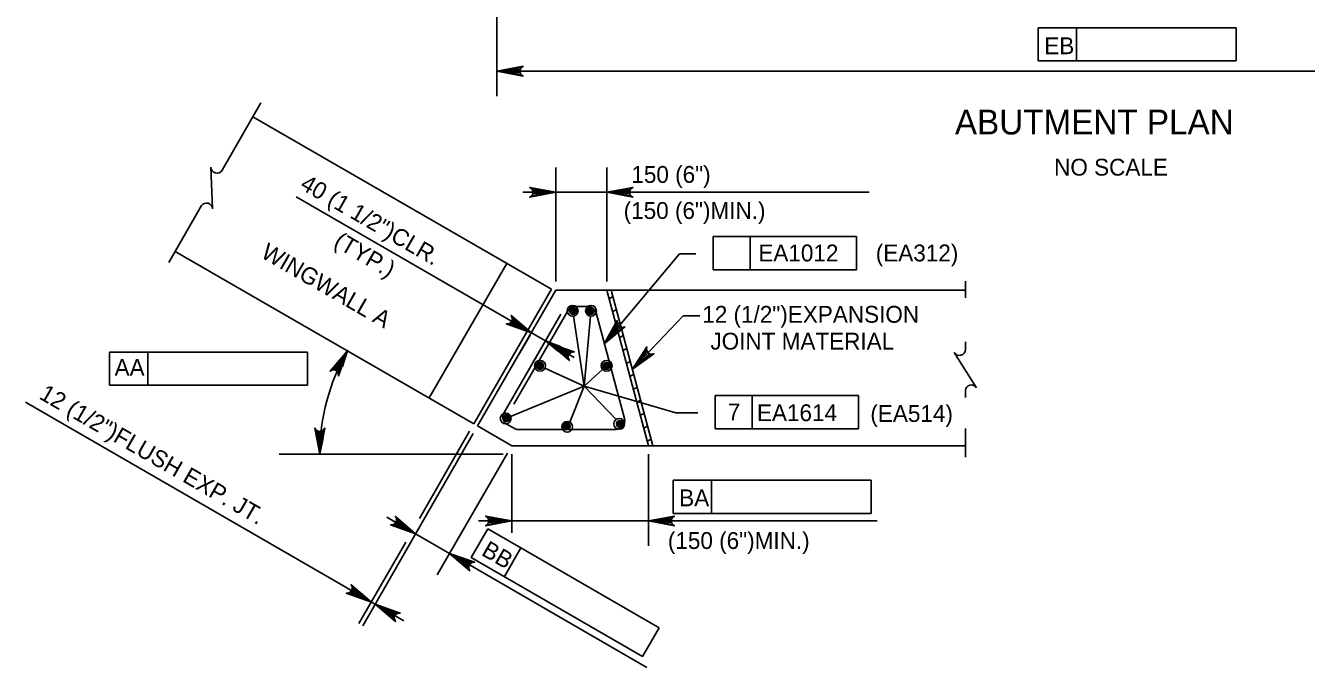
# Model space of a CAD drawing. Extents: x 634540 to 640306, y 296059 to 300275.
# Drawn here: x 638529.9 to 638758.2, y 298120 to 298234.3 of the extents above; entities that cross this region are included whole.
import ezdxf

# ---------------------------------------------------------------- set-up
doc = ezdxf.new("R2010")
doc.units = 0
for name, color, linetype in [('10', 7, 'Continuous'), ('3', 7, 'Continuous'), ('4', 7, 'Continuous'), ('5', 7, 'Continuous')]:
    doc.layers.add(name, color=color, linetype=linetype)

msp = doc.modelspace()

# ---------------------------------------------------------------- linework, layer by layer
at = {"layer": '10'}
for p, q in [((638623.63, 298187.38), (638570.4, 298218.11)), ((638609.79, 298163.4), (638556.56, 298194.13)), ((638615.64, 298191.99), (638601.8, 298168.01)), ((638623.63, 298187.38), (638609.79, 298163.4)), ((638624.41, 298187.19), (638610.45, 298163.02)), ((638697.41, 298187.19), (638624.41, 298187.19)), ((638633.47, 298187.19), (638640.89, 298159.51)), ((638634.27, 298187.19), (638641.69, 298159.51)), ((638634.57, 298186.06), (638633.88, 298185.67)), ((638635.19, 298183.76), (638634.5, 298183.36)), ((638635.81, 298181.45), (638635.12, 298181.05)), ((638636.42, 298179.14), (638635.73, 298178.74)), ((638637.04, 298176.84), (638636.35, 298176.44)), ((638637.66, 298174.53), (638636.97, 298174.13)), ((638638.28, 298172.22), (638637.59, 298171.82)), ((638638.9, 298169.91), (638638.21, 298169.52)), ((638639.51, 298167.61), (638638.82, 298167.21)), ((638640.13, 298165.3), (638639.44, 298164.9)), ((638616.53, 298159.51), (638610.45, 298163.02)), ((638640.75, 298162.99), (638640.06, 298162.6)), ((638697.41, 298159.51), (638616.53, 298159.51)), ((638641.37, 298160.69), (638640.68, 298160.29))]:
    msp.add_line(p, q, dxfattribs=at)
at = {"layer": '3'}
for p, q in [((638613.9, 298270.52), (638613.9, 298221.78)), ((638710.38, 298233.94), (638717.22, 298233.94)), ((638710.38, 298228.04), (638710.38, 298233.94)), ((638717.22, 298228.04), (638717.22, 298233.94)), ((638717.22, 298233.94), (638745.68, 298233.94)), ((638745.68, 298233.94), (638745.68, 298228.04)), ((638745.68, 298228.04), (638710.38, 298228.04)), ((638613.9, 298226.21), (638842.16, 298226.21)), ((638624.41, 298188.73), (638624.41, 298209.09)), ((638633.47, 298188.73), (638633.47, 298209.09)), ((638624.41, 298204.66), (638618.51, 298204.66)), ((638633.47, 298204.66), (638624.41, 298204.66)), ((638633.47, 298204.66), (638680.27, 298204.66)), ((638614.93, 298182.57), (638578.12, 298203.82)), ((638652.45, 298196.76), (638677.99, 298196.76)), ((638652.45, 298190.86), (638652.45, 298196.76)), ((638659.04, 298190.86), (638659.04, 298196.76)), ((638677.99, 298196.76), (638677.99, 298190.86)), ((638633.04, 298177.65), (638646.42, 298193.7)), ((638646.42, 298193.7), (638649.37, 298193.7)), ((638677.99, 298190.86), (638652.45, 298190.86)), ((638620.04, 298179.62), (638614.93, 298182.57)), ((638629.44, 298170.14), (638627.53, 298182.58)), ((638630.58, 298182.58), (638629.44, 298170.14)), ((638638.04, 298173.12), (638647.08, 298182.63)), ((638647.08, 298182.63), (638650.04, 298182.63)), ((638622.54, 298178.18), (638620.04, 298179.62)), ((638619.8, 298179.2), (638617.83, 298175.78)), ((638622.3, 298177.76), (638620.32, 298174.34)), ((638623.21, 298177.79), (638627.65, 298175.23)), ((638544.82, 298176.19), (638551.67, 298176.19)), ((638544.82, 298170.28), (638544.82, 298176.19)), ((638551.67, 298170.28), (638551.67, 298176.19)), ((638551.67, 298176.19), (638580.13, 298176.19)), ((638580.13, 298170.28), (638580.13, 298176.19)), ((638629.44, 298170.14), (638622.46, 298173.34)), ((638632.74, 298173.1), (638629.44, 298170.14)), ((638580.13, 298170.28), (638544.82, 298170.28)), ((638629.44, 298170.14), (638616.34, 298164.72)), ((638626.89, 298163.71), (638629.44, 298170.14)), ((638629.44, 298170.14), (638645.77, 298165.38)), ((638635.15, 298164.18), (638629.44, 298170.14)), ((638652.79, 298168.44), (638678.33, 298168.44)), ((638652.79, 298162.54), (638652.79, 298168.44)), ((638659.39, 298162.54), (638659.39, 298168.44)), ((638678.33, 298168.44), (638678.33, 298162.54)), ((638586.4, 298134.61), (638529.88, 298167.24)), ((638645.77, 298165.38), (638649.72, 298165.38)), ((638609.69, 298161.69), (638589.97, 298127.44)), ((638609.02, 298162.07), (638600.09, 298146.55)), ((638678.33, 298162.54), (638652.79, 298162.54)), ((638615, 298157.97), (638575.09, 298157.97)), ((638615.77, 298158.17), (638603.24, 298136.49)), ((638616.53, 298157.97), (638616.53, 298143.98)), ((638640.89, 298157.97), (638640.89, 298141.68)), ((638645.3, 298147.44), (638645.3, 298153.35)), ((638645.3, 298153.35), (638652.14, 298153.35)), ((638652.14, 298147.44), (638652.14, 298153.35)), ((638652.14, 298153.35), (638680.6, 298153.35)), ((638680.6, 298153.35), (638680.6, 298147.44)), ((638680.6, 298147.44), (638645.3, 298147.44)), ((638596.82, 298145.31), (638594.27, 298146.79)), ((638613.58, 298146.11), (638610.63, 298146.11)), ((638616.53, 298146.11), (638640.89, 298146.11)), ((638643.84, 298146.11), (638646.79, 298146.11)), ((638646.79, 298146.11), (638681.66, 298146.11)), ((638599.38, 298143.83), (638605.46, 298140.32)), ((638609.3, 298139.6), (638612.25, 298144.72)), ((638612.25, 298144.72), (638618.18, 298141.3)), ((638597.66, 298142.34), (638589.3, 298127.82)), ((638615.23, 298136.18), (638618.18, 298141.3)), ((638618.18, 298141.3), (638642.83, 298127.07)), ((638608.01, 298138.85), (638610.57, 298137.37)), ((638639.87, 298121.95), (638609.3, 298139.6)), ((638610.57, 298137.37), (638640.63, 298120.02)), ((638588.96, 298133.13), (638586.4, 298134.61)), ((638592.18, 298131.27), (638591.52, 298131.65)), ((638594.74, 298129.79), (638597.3, 298128.32)), ((638642.83, 298127.07), (638639.87, 298121.95))]:
    msp.add_line(p, q, dxfattribs=at)
for points in [[(638613.9, 298226.21), (638618.56, 298227.09), (638618.2, 298226.84), (638618.01, 298226.53), (638617.96, 298226.21), (638618.01, 298225.9), (638618.2, 298225.59), (638618.56, 298225.34), (638613.9, 298226.21), (638618.2, 298225.59), (638618.01, 298225.9), (638613.9, 298226.21), (638617.96, 298226.21), (638618.01, 298226.53), (638613.9, 298226.21), (638618.2, 298226.84)], [(638624.41, 298204.66), (638619.75, 298203.79), (638620.11, 298204.04), (638620.29, 298204.35), (638620.35, 298204.66), (638620.29, 298204.97), (638620.11, 298205.29), (638619.75, 298205.53), (638624.41, 298204.66), (638620.11, 298205.29), (638620.29, 298204.97), (638624.41, 298204.66), (638620.35, 298204.66), (638620.29, 298204.35), (638624.41, 298204.66), (638620.11, 298204.04)], [(638633.47, 298204.66), (638638.13, 298205.53), (638637.77, 298205.29), (638637.59, 298204.97), (638637.53, 298204.66), (638637.59, 298204.35), (638637.77, 298204.04), (638638.13, 298203.79), (638633.47, 298204.66), (638637.77, 298204.04), (638637.59, 298204.35), (638633.47, 298204.66), (638637.53, 298204.66), (638637.59, 298204.97), (638633.47, 298204.66), (638637.77, 298205.29)], [(638620.04, 298179.62), (638615.57, 298181.19), (638616, 298181.23), (638616.32, 298181.41), (638616.52, 298181.65), (638616.63, 298181.95), (638616.63, 298182.31), (638616.44, 298182.71), (638620.04, 298179.62), (638616.63, 298182.31), (638616.63, 298181.95), (638620.04, 298179.62), (638616.52, 298181.65), (638616.32, 298181.41), (638620.04, 298179.62), (638616, 298181.23)], [(638633.04, 298177.65), (638635.35, 298181.79), (638635.31, 298181.36), (638635.43, 298181.01), (638635.64, 298180.77), (638635.91, 298180.61), (638636.27, 298180.56), (638636.7, 298180.67), (638633.04, 298177.65), (638636.27, 298180.56), (638635.91, 298180.61), (638633.04, 298177.65), (638635.64, 298180.77), (638635.43, 298181.01), (638633.04, 298177.65), (638635.31, 298181.36)], [(638623.21, 298177.79), (638627.68, 298176.22), (638627.24, 298176.18), (638626.93, 298176), (638626.72, 298175.76), (638626.61, 298175.46), (638626.62, 298175.1), (638626.81, 298174.7), (638623.21, 298177.79), (638626.62, 298175.1), (638626.61, 298175.46), (638623.21, 298177.79), (638626.72, 298175.76), (638626.93, 298176), (638623.21, 298177.79), (638627.24, 298176.18)], [(638587.25, 298176.41), (638585.68, 298171.94), (638585.64, 298172.38), (638585.46, 298172.69), (638585.22, 298172.89), (638584.92, 298173), (638584.56, 298173), (638584.16, 298172.81), (638587.25, 298176.41), (638584.56, 298173), (638584.92, 298173), (638587.25, 298176.41), (638585.22, 298172.89), (638585.46, 298172.69), (638587.25, 298176.41), (638585.64, 298172.38)], [(638638.04, 298173.12), (638640.62, 298177.1), (638640.55, 298176.67), (638640.65, 298176.32), (638640.84, 298176.06), (638641.1, 298175.89), (638641.45, 298175.8), (638641.88, 298175.89), (638638.04, 298173.12), (638641.45, 298175.8), (638641.1, 298175.89), (638638.04, 298173.12), (638640.84, 298176.06), (638640.65, 298176.32), (638638.04, 298173.12), (638640.55, 298176.67)], [(638582.32, 298157.97), (638581.44, 298162.63), (638581.69, 298162.27), (638582.01, 298162.09), (638582.32, 298162.03), (638582.63, 298162.09), (638582.94, 298162.27), (638583.19, 298162.63), (638582.32, 298157.97), (638582.94, 298162.27), (638582.63, 298162.09), (638582.32, 298157.97), (638582.32, 298162.03), (638582.01, 298162.09), (638582.32, 298157.97), (638581.69, 298162.27)], [(638599.4, 298143.82), (638594.93, 298145.4), (638595.36, 298145.43), (638595.68, 298145.61), (638595.88, 298145.86), (638595.99, 298146.15), (638595.99, 298146.52), (638595.8, 298146.91), (638599.4, 298143.82), (638595.99, 298146.52), (638595.99, 298146.15), (638599.4, 298143.82), (638595.88, 298145.86), (638595.68, 298145.61), (638599.4, 298143.82), (638595.36, 298145.43)], [(638616.53, 298146.11), (638611.87, 298145.24), (638612.23, 298145.48), (638612.42, 298145.8), (638612.47, 298146.11), (638612.42, 298146.42), (638612.23, 298146.73), (638611.87, 298146.98), (638616.53, 298146.11), (638612.23, 298146.73), (638612.42, 298146.42), (638616.53, 298146.11), (638612.47, 298146.11), (638612.42, 298145.8), (638616.53, 298146.11), (638612.23, 298145.48)], [(638640.89, 298146.11), (638645.55, 298146.98), (638645.19, 298146.73), (638645.01, 298146.42), (638644.95, 298146.11), (638645.01, 298145.8), (638645.19, 298145.48), (638645.55, 298145.24), (638640.89, 298146.11), (638645.19, 298145.48), (638645.01, 298145.8), (638640.89, 298146.11), (638644.95, 298146.11), (638645.01, 298146.42), (638640.89, 298146.11), (638645.19, 298146.73)], [(638605.46, 298140.32), (638609.93, 298138.75), (638609.5, 298138.72), (638609.18, 298138.54), (638608.98, 298138.29), (638608.87, 298138), (638608.87, 298137.63), (638609.06, 298137.24), (638605.46, 298140.32), (638608.87, 298137.63), (638608.87, 298138), (638605.46, 298140.32), (638608.98, 298138.29), (638609.18, 298138.54), (638605.46, 298140.32), (638609.5, 298138.72)], [(638591.51, 298131.66), (638587.04, 298133.23), (638587.47, 298133.27), (638587.79, 298133.45), (638587.99, 298133.69), (638588.1, 298133.99), (638588.1, 298134.35), (638587.91, 298134.75), (638591.51, 298131.66), (638588.1, 298134.35), (638588.1, 298133.99), (638591.51, 298131.66), (638587.99, 298133.69), (638587.79, 298133.45), (638591.51, 298131.66), (638587.47, 298133.27)], [(638592.19, 298131.26), (638596.67, 298129.69), (638596.23, 298129.66), (638595.91, 298129.48), (638595.71, 298129.24), (638595.6, 298128.94), (638595.61, 298128.58), (638595.79, 298128.18), (638592.19, 298131.26), (638595.61, 298128.58), (638595.6, 298128.94), (638592.19, 298131.26), (638595.71, 298129.24), (638595.91, 298129.48), (638592.19, 298131.26), (638596.23, 298129.66)]]:
    msp.add_lwpolyline(points, dxfattribs=at)
for points in [[(638616.85, 298226.7), (638616.85, 298225.72), (638613.9, 298226.21)], [(638621.46, 298205.15), (638621.46, 298204.17), (638624.41, 298204.66)], [(638636.42, 298205.15), (638636.42, 298204.17), (638633.47, 298204.66)], [(638617.73, 298181.52), (638617.24, 298180.67), (638620.04, 298179.62)], [(638634.55, 298180.24), (638635.31, 298179.61), (638633.04, 298177.65)], [(638625.34, 298177.13), (638624.85, 298176.28), (638622.54, 298178.18)], [(638586.34, 298173.63), (638585.47, 298174.09), (638587.28, 298176.47)], [(638639.71, 298175.6), (638640.43, 298174.92), (638638.04, 298173.12)], [(638581.94, 298160.94), (638582.93, 298160.9), (638582.32, 298157.97)], [(638597.07, 298145.74), (638596.58, 298144.88), (638599.38, 298143.83)], [(638613.58, 298146.6), (638613.58, 298145.62), (638616.53, 298146.11)], [(638643.84, 298146.6), (638643.84, 298145.62), (638640.89, 298146.11)], [(638608.26, 298139.27), (638607.77, 298138.42), (638605.46, 298140.32)], [(638589.21, 298133.56), (638588.71, 298132.7), (638591.52, 298131.65)], [(638594.98, 298130.22), (638594.49, 298129.37), (638592.18, 298131.27)]]:
    msp.add_lwpolyline(points, close=True, dxfattribs=at)
for centre in [(638627.39, 298183.54), (638630.67, 298183.54), (638621.58, 298173.75), (638633.45, 298173.75), (638615.45, 298164.35), (638626.42, 298162.87), (638635.7, 298163.39)]:
    msp.add_circle(centre, 0.962, dxfattribs=at)
msp.add_arc((638619.33, 298157.97), 37.01, 150.1038, 180, dxfattribs=at)
at = {"layer": '4'}
for p, q in [((638571.83, 298220.59), (638564.9, 298208.59)), ((638562.91, 298209.12), (638563.2, 298201.7)), ((638561.26, 298202.28), (638555.42, 298192.16)), ((638697.41, 298188.84), (638697.41, 298185.83)), ((638697.41, 298178.03), (638697.41, 298176.65)), ((638695.42, 298176.11), (638699.37, 298169.83)), ((638697.41, 298169.36), (638697.41, 298168.12)), ((638697.41, 298162.58), (638697.41, 298157.49))]:
    msp.add_line(p, q, dxfattribs=at)
for centre, start, end in [((638563.98, 298209.12), 180, 330), ((638562.13, 298201.66), 2.1328, 144.6714), ((638696.34, 298176.65), 210, 0), ((638698.47, 298169.26), 32.1328, 174.6714)]:
    msp.add_arc(centre, 1.07, start, end, dxfattribs=at)
at = {"layer": '5'}
for p, q in [((638630.08, 298184.3), (638627.85, 298184.3)), ((638625.27, 298182.91), (638615.16, 298165.4)), ((638626.52, 298183.54), (638616.91, 298166.88)), ((638631.56, 298183.17), (638636.61, 298164.33)), ((638616.95, 298162.6), (638615.73, 298163.3)), ((638635.13, 298162.39), (638617.72, 298162.39))]:
    msp.add_line(p, q, dxfattribs=at)
for centre, radius in [((638627.44, 298183.53), 0.625), ((638627.44, 298183.53), 0.469), ((638630.62, 298183.51), 0.625), ((638630.62, 298183.51), 0.469), ((638627.44, 298183.53), 0.313), ((638627.44, 298183.53), 0.156), ((638630.62, 298183.51), 0.313), ((638630.62, 298183.51), 0.156), ((638621.58, 298173.74), 0.625), ((638621.58, 298173.74), 0.469), ((638621.58, 298173.74), 0.313), ((638621.58, 298173.74), 0.156), ((638633.41, 298173.72), 0.625), ((638633.41, 298173.72), 0.469), ((638633.41, 298173.72), 0.313), ((638633.41, 298173.72), 0.156), ((638615.6, 298164.43), 0.625), ((638615.6, 298164.43), 0.469), ((638615.6, 298164.43), 0.313), ((638615.6, 298164.43), 0.156), ((638626.33, 298162.96), 0.625), ((638626.33, 298162.96), 0.469), ((638635.86, 298163.38), 0.625), ((638635.86, 298163.38), 0.469), ((638635.86, 298163.38), 0.313), ((638635.86, 298163.38), 0.156), ((638626.33, 298162.96), 0.313), ((638626.33, 298162.96), 0.156)]:
    msp.add_circle(centre, radius, dxfattribs=at)
for centre, start, end in [((638627.85, 298182.77), 90, 150), ((638630.08, 298182.77), 15, 90), ((638616.5, 298164.63), 150, 240), ((638635.13, 298163.93), 270, 15), ((638617.72, 298163.93), 240, 270)]:
    msp.add_arc(centre, 1.54, start, end, dxfattribs=at)

# ---------------------------------------------------------------- texts
at = {"layer": '3'}
for s, height, p in [('EB', 3, (638711.47, 298229.25)), ('ABUTMENT PLAN', 4.4294, (638695.54, 298214.95)), ('150 (6")', 3, (638637.86, 298206.33)), ('NO SCALE', 3, (638713.22, 298207.62)), ('(150 (6")MIN.)', 3.0001, (638636.49, 298199.9)), ('EA1012', 3, (638660.5, 298192.34)), ('(EA312)', 3, (638681.43, 298192.34)), ('12 (1/2")EXPANSION', 3.0001, (638650.5, 298181.41)), ('JOINT MATERIAL', 3.0001, (638651.95, 298176.63)), ('AA', 3, (638545.74, 298171.96)), ('7', 3, (638655.05, 298164.02)), ('EA1614', 3, (638660.25, 298163.88)), ('(EA514)', 3, (638680.47, 298163.74)), ('BA', 3, (638646.39, 298148.72)), ('(150 (6")MIN.)', 3.0001, (638644.37, 298141.11))]:
    msp.add_text(s, height=height, dxfattribs=at).set_placement(p)
for s, height, p in [(' 40 (1 1/2")CLR.', 3.0001, (638577.65, 298205.93)), ('WINGWALL A', 3, (638571.62, 298193.16)), ('(TYP.)', 3, (638584.6, 298195.13)), ('12 (1/2")FLUSH EXP. JT.', 3.0001, (638532.1, 298167.99)), ('BB', 3, (638610.95, 298140.11))]:
    msp.add_text(s, height=height, rotation=330, dxfattribs=at).set_placement(p)

doc.saveas('drawing.dxf')
